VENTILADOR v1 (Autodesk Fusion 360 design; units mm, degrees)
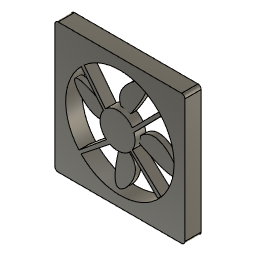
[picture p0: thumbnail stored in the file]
sketch "Sketch1" plane through (0, 0, 0) normal (0, 1, 0) x axis (1, 0, 0)
  line L1 (120, 0) -> (0, 0)
  line L2 (120, -120) -> (120, 0)
  line L3 (0, -120) -> (120, -120)
  line L4 (0, 0) -> (0, -120)
  point P1 (0, 0)
  point P2 (0, 0)
  point P3 (120, 0)
  point P5 (0, -120)
  horizontal L1
  vertical L2
  horizontal L3
  vertical L4
  coincident P1 P2
  dimension "d1" distance P2 P3 = 120
  dimension "d2" distance P2 P5 = 120
extrude "Extrude1" new body sketch "Sketch1" along normal blind 15
sketch "Sketch2" plane through (0, 0, 0) normal (0, -1, 0) x axis (1, 0, 0)
  line L1 (0, 120) -> (120, 120)
  line L2 (0, 0) -> (0, 120)
  line L3 (120, 0) -> (0, 0)
  line L4 (120, 120) -> (120, 0)
  circle C1 centre (60, 60) radius 50
  dimension "d5" diameter C1 = 100
extrude "Extrude2" cut sketch "Sketch2" profile of C1 distance 20
sketch "Sketch3" plane through (0, 0, 0) normal (0, 1, 0) x axis (1, 0, 0)
  line L1 (95, -25) -> (69.8084, -49.7859)
  line L2 (96.1204, -94.6636) -> (71.4078, -69.5464)
  line L3 (44.8151, -70.2307) -> (23.816, -95.5593)
  line L4 (50.792, -46.161) -> (24, -25)
  line L5 (27.1087, -97.4894) -> (46.6834, -72.3674)
  line L6 (98.0341, -92.1823) -> (72.9099, -66.6469)
  line L7 (97.8108, -27.8066) -> (71.4947, -51.9813)
  line L8 (22, -27) -> (47.5374, -48.2633)
  line L9 (27.1087, -97.4894) -> (23.816, -95.5593)
  line L10 (98.0341, -92.1823) -> (96.1204, -94.6636)
  line L11 (95, -25) -> (97.8108, -27.8066)
  line L12 (22, -27) -> (24, -25)
  circle C1 centre (57.8749, -60.6967) radius 16.1696
  point P3 (69.8084, -49.7859)
  point P8 (44.8151, -70.2307)
  point P10 (50.792, -46.161)
  point P5 (71.4078, -69.5464)
  point P11 (46.6834, -72.3674)
  point P13 (72.9099, -66.6469)
  point P15 (71.4947, -51.9813)
  point P17 (47.5374, -48.2633)
  perpendicular L1 L2
  coincident C1 P3
  coincident C1 P8
  coincident C1 P10
  coincident C1 P5
  coincident C1 P11
  coincident C1 P13
  parallel L2 L6
  coincident C1 P15
  coincident C1 P17
extrude "Extrude3" add sketch "Sketch3" along normal blind 10
fillet "Fillet1" radius 3
fillet "Fillet2" radius 3
fillet "Fillet3" radius 3
fillet "Fillet4" radius 3
sketch "Sketch4" plane through (0, 15, 0) normal (0, 1, 0) x axis (-1, 0, 0)
  line L1 (0, 117) -> (0, 3)
  line L2 (-117, 120) -> (-3, 120)
  line L3 (-120, 3) -> (-120, 117)
  line L4 (-3, 0) -> (-117, 0)
  curve K1 (-55.9929, 76.7737) -> (-65, 75)
  curve K2 (-42.3656, 55.7132) -> (-42.3656, 64.7391)
  curve K3 (-61.8332, 45) -> (-55, 45)
  curve K4 (-74.2217, 62.2614) -> (-72.6081, 55.7132)
  curve K5 (-72.6081, 55.7132) -> (-74.2217, 62.2614)
  curve K6 (-55, 45) -> (-61.8332, 45)
  curve K7 (-42.3656, 55.7132) -> (-42.3656, 64.7391)
  curve K8 (-55.9929, 76.7737) -> (-65, 75)
  arc A1 centre (-3, 3) radius 3 clockwise from (0, 3) to (-3, 0)
  arc A2 centre (-3, 117) radius 3 clockwise from (-3, 120) to (0, 117)
  arc A3 centre (-117, 117) radius 3 clockwise from (-120, 117) to (-117, 120)
  arc A4 centre (-117, 3) radius 3 clockwise from (-117, 0) to (-120, 3)
  circle C1 centre (-60, 60) radius 50
  point P16 (-77.8984, 106.6867)
  point P20 (-11.884, 73.5958)
  point P24 (-55, 10.2506)
  point P28 (-108.4695, 47.7238)
  coincident C1 P16
  coincident C1 P20
  coincident C1 P24
  coincident C1 P28
extrude "Extrude4" new body sketch "Sketch4" profile of C1 K1 K2 K3 K4 K5 K6 K7 K8 along normal blind 5
move "Move1"
move "Move2"
move "Move3"
move "Move4"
